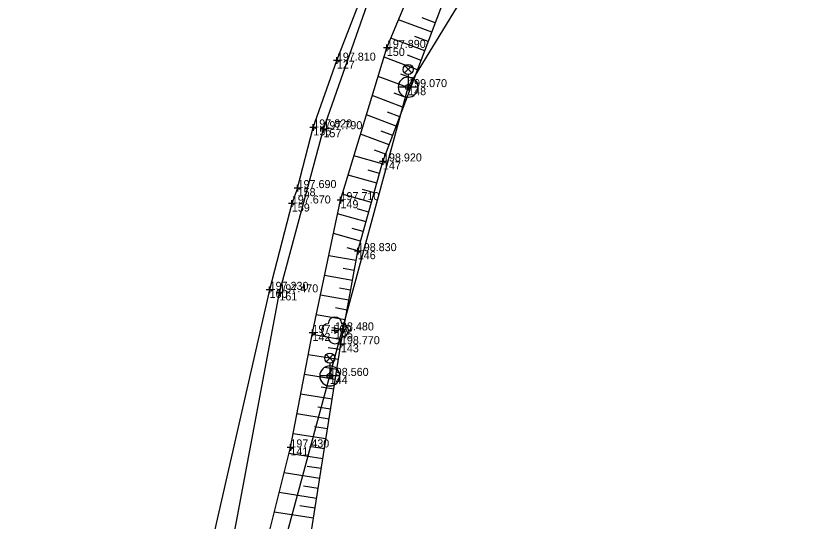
# Model space of a CAD drawing. Extents: x -744883 to -744469, y -966832 to -966374.
# Drawn here: x -744789.9 to -744731.6, y -966546.7 to -966508.9 of the extents above; entities that cross this region are included whole.
import ezdxf

# ---------------------------------------------------------------- set-up
doc = ezdxf.new("R2010")
doc.units = 0
for name, color, linetype in [('Body polohopisu', 7, 'Continuous'), ('Doplňkové značky', 7, 'Continuous'), ('Ploty_opěrné zdi', 7, 'Continuous'), ('Rozhraní ploch', 7, 'Continuous'), ('Stromy_porost', 7, 'Continuous'), ('Vrstva 132', 7, 'Continuous'), ('Vstup na pozemek', 7, 'Continuous'), ('Výškopis', 7, 'Continuous'), ('Výšky bodů', 7, 'Continuous'), ('Značky IS', 7, 'Continuous'), ('Čísla bodů', 7, 'Continuous')]:
    doc.layers.add(name, color=color, linetype=linetype)

msp = doc.modelspace()

# ---------------------------------------------------------------- linework, layer by layer
at = {"layer": 'Body polohopisu'}
for p, q in [((-744762.2, -966511.33), (-744762.45, -966511.33)), ((-744762.2, -966511.33), (-744762.2, -966511.08)), ((-744762.2, -966511.33), (-744761.95, -966511.33)), ((-744762.2, -966511.33), (-744762.2, -966511.58)), ((-744765.93, -966512.28), (-744766.18, -966512.28)), ((-744765.93, -966512.28), (-744765.93, -966512.03)), ((-744765.93, -966512.28), (-744765.68, -966512.28)), ((-744765.93, -966512.28), (-744765.93, -966512.53)), ((-744760.61, -966514.26), (-744760.86, -966514.26)), ((-744760.61, -966514.26), (-744760.61, -966514.01)), ((-744760.61, -966514.26), (-744760.36, -966514.26)), ((-744760.61, -966514.26), (-744760.61, -966514.51)), ((-744767.69, -966517.27), (-744767.69, -966517.02)), ((-744766.93, -966517.4), (-744766.93, -966517.15)), ((-744767.69, -966517.27), (-744767.94, -966517.27)), ((-744767.69, -966517.27), (-744767.44, -966517.27)), ((-744767.69, -966517.27), (-744767.69, -966517.52)), ((-744766.93, -966517.4), (-744767.18, -966517.4)), ((-744766.93, -966517.4), (-744766.68, -966517.4)), ((-744766.93, -966517.4), (-744766.93, -966517.65)), ((-744762.49, -966519.81), (-744762.74, -966519.81)), ((-744762.49, -966519.81), (-744762.49, -966519.56)), ((-744762.49, -966519.81), (-744762.24, -966519.81)), ((-744762.49, -966519.81), (-744762.49, -966520.06)), ((-744768.86, -966521.8), (-744769.11, -966521.8)), ((-744768.86, -966521.8), (-744768.86, -966521.55)), ((-744768.86, -966521.8), (-744768.61, -966521.8)), ((-744768.86, -966521.8), (-744768.86, -966522.05)), ((-744769.29, -966522.95), (-744769.54, -966522.95)), ((-744769.29, -966522.95), (-744769.29, -966522.7)), ((-744769.29, -966522.95), (-744769.04, -966522.95)), ((-744769.29, -966522.95), (-744769.29, -966523.2)), ((-744765.66, -966522.7), (-744765.91, -966522.7)), ((-744765.66, -966522.7), (-744765.66, -966522.45)), ((-744765.66, -966522.7), (-744765.41, -966522.7)), ((-744765.66, -966522.7), (-744765.66, -966522.95)), ((-744764.37, -966526.51), (-744764.62, -966526.51)), ((-744764.37, -966526.51), (-744764.37, -966526.26)), ((-744764.37, -966526.51), (-744764.12, -966526.51)), ((-744764.37, -966526.51), (-744764.37, -966526.76)), ((-744770.95, -966529.4), (-744771.2, -966529.4)), ((-744770.95, -966529.4), (-744770.95, -966529.15)), ((-744770.95, -966529.4), (-744770.7, -966529.4)), ((-744770.95, -966529.4), (-744770.95, -966529.65)), ((-744770.22, -966529.59), (-744770.22, -966529.34)), ((-744770.22, -966529.59), (-744770.47, -966529.59)), ((-744770.22, -966529.59), (-744769.97, -966529.59)), ((-744770.22, -966529.59), (-744770.22, -966529.84)), ((-744766.07, -966532.43), (-744766.07, -966532.18)), ((-744767.75, -966532.62), (-744768, -966532.62)), ((-744767.75, -966532.62), (-744767.75, -966532.37)), ((-744767.75, -966532.62), (-744767.5, -966532.62)), ((-744767.75, -966532.62), (-744767.75, -966532.87)), ((-744766.07, -966532.43), (-744766.32, -966532.43)), ((-744766.07, -966532.43), (-744765.82, -966532.43)), ((-744766.07, -966532.43), (-744766.07, -966532.68)), ((-744765.63, -966533.46), (-744765.88, -966533.46)), ((-744765.63, -966533.46), (-744765.63, -966533.21)), ((-744765.63, -966533.46), (-744765.38, -966533.46)), ((-744765.63, -966533.46), (-744765.63, -966533.71)), ((-744766.46, -966535.83), (-744766.71, -966535.83)), ((-744766.46, -966535.83), (-744766.46, -966535.58)), ((-744766.46, -966535.83), (-744766.21, -966535.83)), ((-744766.46, -966535.83), (-744766.46, -966536.08)), ((-744769.4, -966541.17), (-744769.4, -966540.92)), ((-744769.4, -966541.17), (-744769.65, -966541.17)), ((-744769.4, -966541.17), (-744769.15, -966541.17)), ((-744769.4, -966541.17), (-744769.4, -966541.42))]:
    msp.add_line(p, q, dxfattribs=at)
at = {"layer": 'Doplňkové značky'}
for p, q in [((-744760.874, -966513.198), (-744760.346, -966512.67)), ((-744760.338, -966513.195), (-744760.866, -966512.666)), ((-744760.61, -966513.31), (-744760.61, -966514.06)), ((-744766.724, -966534.768), (-744766.196, -966534.24)), ((-744766.188, -966534.765), (-744766.716, -966534.236)), ((-744766.46, -966534.88), (-744766.46, -966535.63))]:
    msp.add_line(p, q, dxfattribs=at)
for centre, radius in [((-744760.61, -966512.935), 0.375), ((-744760.61, -966514.26), 0.2), ((-744766.46, -966534.505), 0.375), ((-744766.46, -966535.83), 0.2)]:
    msp.add_circle(centre, radius, dxfattribs=at)
at = {"layer": 'Ploty_opěrné zdi'}
for points in [[(-744768.03, -966548.68), (-744765.63, -966533.46), (-744764.37, -966526.51), (-744762.49, -966519.81), (-744756.19, -966503.11), (-744754.76, -966499.94), (-744743.36, -966484.97)], [(-744765.93, -966512.28), (-744760.87, -966499.15)], [(-744768.86, -966521.8), (-744767.69, -966517.27), (-744765.93, -966512.28)], [(-744769.29, -966522.95), (-744770.95, -966529.4)], [(-744770.95, -966529.4), (-744777.79, -966559.41), (-744788.97, -966586.23)]]:
    msp.add_lwpolyline(points, dxfattribs=at)
at = {"layer": 'Rozhraní ploch'}
for points in [[(-744768.03, -966548.68), (-744773.19, -966556.41), (-744769.4, -966541.17), (-744767.75, -966532.62), (-744765.66, -966522.7), (-744762.2, -966511.33), (-744758.67, -966502.84), (-744756.29, -966498.23), (-744753.94, -966494.54), (-744748.19, -966487.33), (-744740.89, -966479.62)], [(-744823.64, -966560.07), (-744824.49, -966561.26), (-744822.69, -966563.25), (-744792.4, -966589.44), (-744789.07, -966589.25), (-744787.02, -966587.43), (-744786.08, -966585.59), (-744781.44, -966572.53), (-744776.99, -966559.6), (-744773.56, -966547.49), (-744770.22, -966529.59), (-744766.93, -966517.4), (-744763.66, -966508.11), (-744759.7, -966498.38), (-744760.87, -966499.15)]]:
    msp.add_lwpolyline(points, dxfattribs=at)
at = {"layer": 'Stromy_porost'}
msp.add_circle((-744766.07, -966532.43), 0.0005, dxfattribs=at)
for centre, start, end in [((-744766.07, -966531.93), 0, 179.99999), ((-744766.57, -966532.43), 89.99999, 269.99999), ((-744765.57, -966532.43), 270, 89.99999), ((-744766.07, -966532.93), 179.99999, 359.99999)]:
    msp.add_arc(centre, 0.5, start, end, dxfattribs=at)
at = {"layer": 'Vrstva 132'}
msp.add_lwpolyline([(-744784.17, -966607.48), (-744776.1, -966571.48), (-744766.46, -966535.83), (-744760.61, -966514.26), (-744741.19, -966482.43), (-744714.51, -966441.91), (-744696.14, -966413.51)], dxfattribs=at)
at = {"layer": 'Vstup na pozemek'}
msp.add_lwpolyline([(-744768.86, -966521.8), (-744769.29, -966522.95)], dxfattribs=at)
at = {"layer": 'Výškopis'}
for points in [[(-744758.847, -966510.154), (-744761.323, -966509.22)], [(-744758.583, -966509.453), (-744759.564, -966509.083)], [(-744759.377, -966511.558), (-744761.899, -966510.606)], [(-744759.112, -966510.856), (-744760.112, -966510.479)], [(-744759.642, -966512.26), (-744760.66, -966511.875)], [(-744759.906, -966512.961), (-744762.409, -966512.017)], [(-744760.436, -966514.365), (-744762.847, -966513.455)], [(-744760.171, -966513.663), (-744761.154, -966513.292)], [(-744760.701, -966515.066), (-744761.647, -966514.71)], [(-744760.965, -966515.768), (-744763.284, -966514.893)], [(-744761.495, -966517.172), (-744763.722, -966516.331)], [(-744761.23, -966516.47), (-744762.139, -966516.127)], [(-744762.024, -966518.575), (-744764.16, -966517.769)], [(-744761.759, -966517.873), (-744762.632, -966517.544)], [(-744762.539, -966519.983), (-744764.653, -966519.39)], [(-744762.289, -966519.277), (-744763.125, -966518.961)], [(-744762.741, -966520.706), (-744763.593, -966520.466)], [(-744762.944, -966521.428), (-744765.09, -966520.826)], [(-744763.349, -966522.872), (-744765.526, -966522.261)], [(-744763.147, -966522.15), (-744764.011, -966521.907)], [(-744763.552, -966523.594), (-744764.419, -966523.351)], [(-744763.754, -966524.316), (-744765.875, -966523.721)], [(-744764.16, -966525.76), (-744766.185, -966525.192)], [(-744763.957, -966525.038), (-744764.786, -966524.806)], [(-744764.362, -966526.482), (-744765.153, -966526.26)], [(-744764.499, -966527.22), (-744766.534, -966526.851)], [(-744764.632, -966527.958), (-744765.455, -966527.809)], [(-744764.766, -966528.696), (-744766.844, -966528.319)], [(-744764.9, -966529.434), (-744765.739, -966529.282)], [(-744765.034, -966530.172), (-744767.153, -966529.787)], [(-744765.168, -966530.91), (-744766.024, -966530.754)], [(-744765.301, -966531.648), (-744767.463, -966531.256)], [(-744765.435, -966532.386), (-744766.308, -966532.227)], [(-744765.569, -966533.124), (-744767.77, -966532.724)], [(-744765.694, -966533.863), (-744766.585, -966533.723)], [(-744765.81, -966534.604), (-744768.064, -966534.249)], [(-744765.927, -966535.345), (-744766.839, -966535.201)], [(-744766.044, -966536.086), (-744768.349, -966535.722)], [(-744766.161, -966536.826), (-744767.093, -966536.679)], [(-744766.278, -966537.567), (-744768.633, -966537.196)], [(-744766.394, -966538.308), (-744767.347, -966538.158)], [(-744766.511, -966539.049), (-744768.917, -966538.67)], [(-744766.628, -966539.79), (-744767.601, -966539.636)], [(-744766.745, -966540.531), (-744769.202, -966540.143)], [(-744766.979, -966542.012), (-744769.51, -966541.613)], [(-744766.862, -966541.272), (-744767.855, -966541.115)], [(-744767.095, -966542.753), (-744768.134, -966542.589)], [(-744767.212, -966543.494), (-744769.874, -966543.074)], [(-744767.446, -966544.976), (-744770.237, -966544.536)], [(-744767.329, -966544.235), (-744768.42, -966544.063)], [(-744767.563, -966545.717), (-744768.705, -966545.536)], [(-744767.68, -966546.457), (-744770.6, -966545.997)]]:
    msp.add_lwpolyline(points, dxfattribs=at)
at = {"layer": 'Značky IS'}
for p, q in [((-744759.863, -966514.26), (-744761.358, -966514.26)), ((-744765.713, -966535.83), (-744767.208, -966535.83))]:
    msp.add_line(p, q, dxfattribs=at)
for centre, start, end in [((-744760.61, -966514.26), 0, 180), ((-744760.61, -966514.26), 180, 0), ((-744766.46, -966535.83), 0, 180), ((-744766.46, -966535.83), 180, 0)]:
    msp.add_arc(centre, 0.747, start, end, dxfattribs=at)

# ---------------------------------------------------------------- texts
at = {"layer": 'Výšky bodů'}
for s, p in [('197.890', (-744762.2, -966511.33)), ('197.810', (-744765.93, -966512.28)), ('199.070', (-744760.61, -966514.26)), ('197.820', (-744767.69, -966517.27)), ('197.790', (-744766.93, -966517.4)), ('198.920', (-744762.49, -966519.81)), ('197.690', (-744768.86, -966521.8)), ('197.670', (-744769.29, -966522.95)), ('197.710', (-744765.66, -966522.7)), ('198.830', (-744764.37, -966526.51)), ('197.230', (-744770.95, -966529.4)), ('197.470', (-744770.22, -966529.59)), ('197.560', (-744767.75, -966532.62)), ('198.480', (-744766.07, -966532.43)), ('198.770', (-744765.63, -966533.46)), ('198.560', (-744766.46, -966535.83)), ('197.430', (-744769.4, -966541.17))]:
    msp.add_text(s, height=0.6, dxfattribs=at).set_placement(p)
at = {"layer": 'Čísla bodů'}
for s, p in [('150', (-744762.2, -966511.93)), ('127', (-744765.93, -966512.88)), ('148', (-744760.61, -966514.86)), ('156', (-744767.69, -966517.87)), ('157', (-744766.93, -966518)), ('147', (-744762.49, -966520.41)), ('158', (-744768.86, -966522.4)), ('159', (-744769.29, -966523.55)), ('149', (-744765.66, -966523.3)), ('146', (-744764.37, -966527.11)), ('160', (-744770.95, -966530)), ('161', (-744770.22, -966530.19)), ('142', (-744767.75, -966533.22)), ('145', (-744766.07, -966533.03)), ('143', (-744765.63, -966534.06)), ('144', (-744766.46, -966536.43)), ('141', (-744769.4, -966541.77))]:
    msp.add_text(s, height=0.6, dxfattribs=at).set_placement(p)

doc.saveas('drawing.dxf')
